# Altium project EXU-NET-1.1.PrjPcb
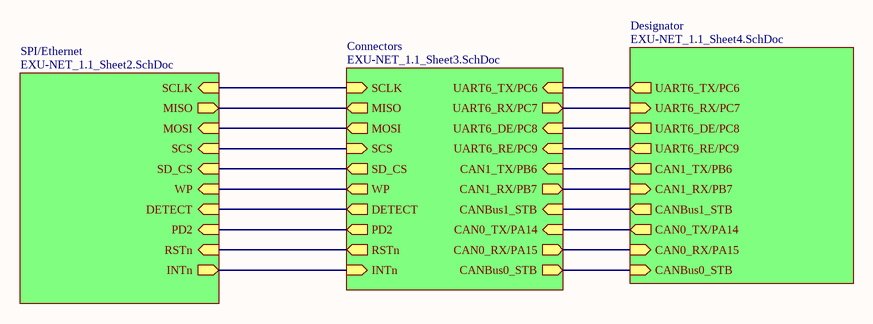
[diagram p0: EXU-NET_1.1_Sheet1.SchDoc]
5 sheets, 112 parts. Net scope: hierarchical (ports join the sheet entries above them; power ports are global).
Board file: EXU-NET_1.1.PcbDoc
Sheets:
  EXU-NET_1.1_Sheet1.SchDoc
    SPI/Ethernet = EXU-NET_1.1_Sheet2.SchDoc
    Connectors = EXU-NET_1.1_Sheet3.SchDoc
    Designator = EXU-NET_1.1_Sheet4.SchDoc
  EXU-NET_1.1_Sheet5.SchDoc

## Sheet EXU-NET_1.1_Sheet1.SchDoc
size A3; SheetNumber: 1; SheetTotal: 5; prj: EXU-NET; Ver: 1.1; Ti: MAIN LIST

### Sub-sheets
Connectors = EXU-NET_1.1_Sheet3.SchDoc: MOSI (out), MISO (out), SCLK (in), SCS (in), SD_CS (out), WP (out), DETECT (out), PD2 (out), CAN1_RX/PB7 (out), CAN1_TX/PB6 (in), UART6_RE/PC9 (in), UART6_DE/PC8 (in), UART6_RX/PC7 (out), UART6_TX/PC6 (in), CANBus1_STB (in), CANBus0_STB (out), CAN0_RX/PA15 (out), CAN0_TX/PA14 (in), RSTn (out), INTn (in)
Designator = EXU-NET_1.1_Sheet4.SchDoc: UART6_TX/PC6 (out), UART6_RX/PC7 (in), UART6_DE/PC8 (out), UART6_RE/PC9 (out), CAN1_TX/PB6 (out), CAN1_RX/PB7 (in), CANBus1_STB (out), CAN0_TX/PA14 (out), CAN0_RX/PA15 (in), CANBus0_STB (in)
SPI/Ethernet = EXU-NET_1.1_Sheet2.SchDoc: MOSI (in), SCS (in), SCLK (in), MISO (out), PD2 (in), DETECT (in), WP (in), SD_CS (in), RSTn (in), INTn (out)

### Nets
CAN0_RX/PA15: sheet Connectors/CAN0_RX/PA15, sheet Designator/CAN0_RX/PA15
CAN0_TX/PA14: sheet Connectors/CAN0_TX/PA14, sheet Designator/CAN0_TX/PA14
CAN1_RX/PB7: sheet Connectors/CAN1_RX/PB7, sheet Designator/CAN1_RX/PB7
CAN1_TX/PB6: sheet Connectors/CAN1_TX/PB6, sheet Designator/CAN1_TX/PB6
CANBus0_STB: sheet Connectors/CANBus0_STB, sheet Designator/CANBus0_STB
CANBus1_STB: sheet Connectors/CANBus1_STB, sheet Designator/CANBus1_STB
MISO: sheet SPI/Ethernet/MISO, sheet Connectors/MISO
MOSI: sheet SPI/Ethernet/MOSI, sheet Connectors/MOSI
RSTn: sheet SPI/Ethernet/RSTn, sheet Connectors/RSTn
SCLK: sheet SPI/Ethernet/SCLK, sheet Connectors/SCLK
SCS: sheet SPI/Ethernet/SCS, sheet Connectors/SCS
UART6_DE/PC8: sheet Connectors/UART6_DE/PC8, sheet Designator/UART6_DE/PC8
UART6_RE/PC9: sheet Connectors/UART6_RE/PC9, sheet Designator/UART6_RE/PC9
UART6_RX/PC7: sheet Connectors/UART6_RX/PC7, sheet Designator/UART6_RX/PC7
UART6_TX/PC6: sheet Connectors/UART6_TX/PC6, sheet Designator/UART6_TX/PC6
NetR53_2: sheet SPI/Ethernet/INTn, sheet Connectors/INTn
(unnamed): sheet SPI/Ethernet/PD2, sheet Connectors/PD2
(unnamed): sheet SPI/Ethernet/DETECT, sheet Connectors/DETECT  [a separate net that carries the same name]
(unnamed): sheet SPI/Ethernet/WP, sheet Connectors/WP  [a separate net that carries the same name]
(unnamed): sheet SPI/Ethernet/SD_CS, sheet Connectors/SD_CS  [a separate net that carries the same name]

## Sheet EXU-NET_1.1_Sheet2.SchDoc
size A3; SheetNumber: 2; SheetTotal: 5; TI: SPI/Ethernet; Prj: EXU-ETH; VER: 1.1
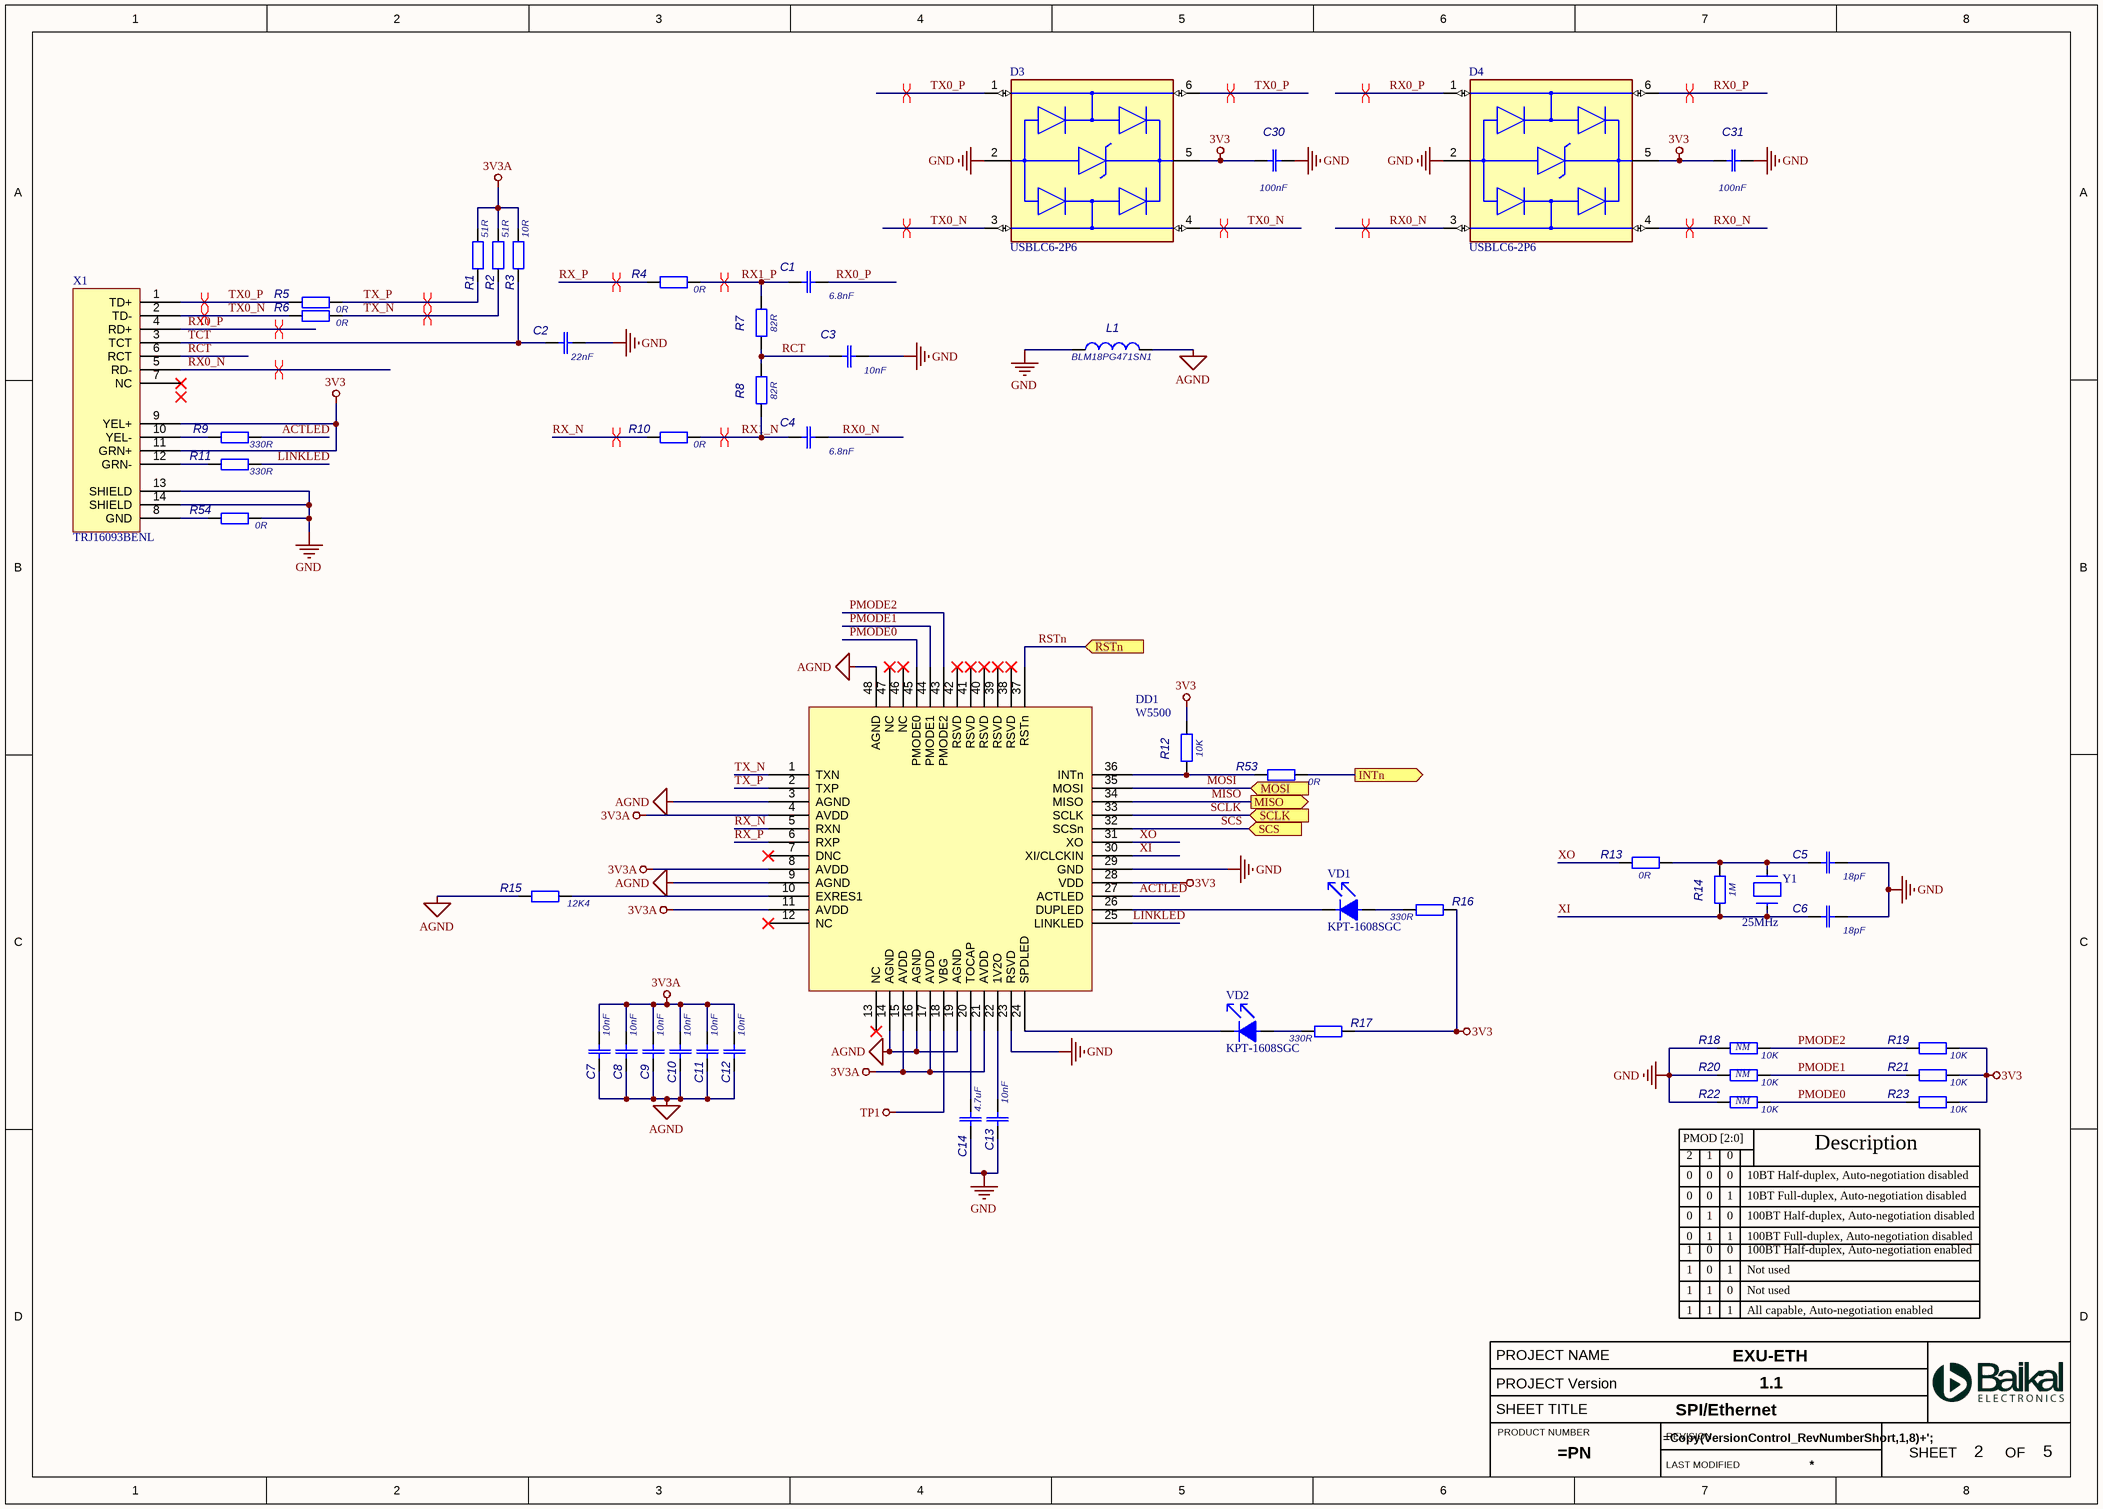
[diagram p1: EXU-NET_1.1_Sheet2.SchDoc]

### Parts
C1  6.8nF  [C0603_CAPC1608X09N]
C2  22nF  [C0603_CAPC1608X09N]
C3  10nF  [C0603_CAPC1608X09N]
C4  6.8nF  [C0603_CAPC1608X09N]
C5  18pF  [C0603_CAPC1608X09N]
C6  18pF  [C0603_CAPC1608X09N]
C7  10nF  [C0603_CAPC1608X09N]
C8  10nF  [C0603_CAPC1608X09N]
C9  10nF  [C0603_CAPC1608X09N]
C10  10nF  [C0603_CAPC1608X09N]
C11  10nF  [C0603_CAPC1608X09N]
C12  10nF  [C0603_CAPC1608X09N]
C13  10nF  [C0603_CAPC1608X09N]
C14  4.7uF  [C0603_CAPC1608X09N]
C30  100nF  [C0603_CAPC1608X09N]
C31  100nF  [C0603_CAPC1608X09N]
D3  USBLC6-2P6  [FP-SOT-666-MFG]
D4  USBLC6-2P6  [FP-SOT-666-MFG]
DD1  W5500  [W5500]
L1  BLM18PG471SN1  [I0603_INDC1608X10N]
R1  51R  [R0603_RESC1608X06N]
R2  51R  [R0603_RESC1608X06N]
R3  10R  [R0603_RESC1608X06N]
R4  0R  [R0603_RESC1608X06N]
R5  0R  [R0603_RESC1608X06N]
R6  0R  [R0603_RESC1608X06N]
R7  82R  [R0603_RESC1608X06N]
R8  82R  [R0603_RESC1608X06N]
R9  330R  [R0603_RESC1608X06N]
R10  0R  [R0603_RESC1608X06N]
R11  330R  [R0603_RESC1608X06N]
R12  10K  [R0603_RESC1608X06N]
R13  0R  [R0603_RESC1608X06N]
R14  1M  [R0603_RESC1608X06N]
R15  12K4  [R0603_RESC1608X06N]
R16  330R  [R0603_RESC1608X06N]
R17  330R  [R0603_RESC1608X06N]
R18  10K  DNP: NM  [R0603_RESC1608X06N]
R19  10K  [R0603_RESC1608X06N]
R20  10K  DNP: NM  [R0603_RESC1608X06N]
R21  10K  [R0603_RESC1608X06N]
R22  10K  DNP: NM  [R0603_RESC1608X06N]
R23  10K  [R0603_RESC1608X06N]
R53  0R  [R0603_RESC1608X06N]
R54  0R  [R0603_RESC1608X06N]
VD1  KPT-1608SGC  [light diode 0603]
VD2  KPT-1608SGC  [light diode 0603]
X1  TRJ16093BENL  [TRJ16093BENL]
Y1  25MHz  [SJK-6C-25.000-16-30-30-C-50-H]

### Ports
INTn (out, see EXU-NET_1.1_Sheet1[5B], EXU-NET_1.1_Sheet3[7D]), MISO (out, see EXU-NET_1.1_Sheet1[5C], EXU-NET_1.1_Sheet3[3C]), MOSI (in, see EXU-NET_1.1_Sheet1[5C], EXU-NET_1.1_Sheet3[3C]), RSTn (in, see EXU-NET_1.1_Sheet1[5B], EXU-NET_1.1_Sheet3[7D]), SCLK (in, see EXU-NET_1.1_Sheet1[5C], EXU-NET_1.1_Sheet3[3C]), SCS (in, see EXU-NET_1.1_Sheet1[5C], EXU-NET_1.1_Sheet3[3C])

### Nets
3V3: C30.1 C31.1 D3.5(VBUS) D4.5(VBUS) DD1.28(VDD) R12.2 R16.1 R17.1 R19.2 R21.2 R23.2 X1.9(YEL+) X1.11(GRN+)
3V3A: C7.2 C8.2 C9.2 C10.2 C11.2 C12.2 DD1.4(AVDD) DD1.8(AVDD) DD1.11(AVDD) DD1.15(AVDD) DD1.17(AVDD) DD1.21(AVDD) R1.2 R2.2 R3.2
AGND: C7.1 C8.1 C9.1 C10.1 C11.1 C12.1 DD1.3(AGND) DD1.9(AGND) DD1.14(AGND) DD1.16(AGND) DD1.19(AGND) DD1.48(AGND) L1.1 R15.1
GND: C2.2 C3.2 C5.2 C6.2 C13.1 C14.1 C30.2 C31.2 D3.2(GND) D4.2(GND) DD1.23(RSVD) DD1.29(GND) L1.2 R18.1 R20.1 R22.1 R54.2 X1.13(SHIELD) X1.14(SHIELD)
TP1: DD1.18(VBG)
ACTLED: DD1.27(ACTLED) R9.2
LINKLED: DD1.25(LINKLED) R11.2
MISO: DD1.34(MISO) ; port MISO
MOSI: DD1.35(MOSI) ; port MOSI
PMODE0: DD1.45(PMODE0) R22.2 R23.1
PMODE1: DD1.44(PMODE1) R20.2 R21.1
PMODE2: DD1.43(PMODE2) R18.2 R19.1
RCT: C3.1 R7.1 R8.2 X1.6(RCT)
RSTn: DD1.37(RSTn) ; port RSTn
RX0_N: C4.2 D4.3(I/O2) D4.4(I/O2) X1.5(RD-)
RX0_P: C1.2 D4.1(I/O1) D4.6(I/O1) X1.4(RD+)
RX1_N: C4.1 R8.1 R10.2
RX1_P: C1.1 R4.2 R7.2
RX_N: DD1.5(RXN) R10.1
RX_P: DD1.6(RXP) R4.1
SCLK: DD1.33(SCLK) ; port SCLK
SCS: DD1.32(SCSn) ; port SCS
TCT: C2.1 R3.1 X1.3(TCT)
TX0_N: D3.3(I/O2) D3.4(I/O2) R6.1 X1.2(TD-)
TX0_P: D3.1(I/O1) D3.6(I/O1) R5.1 X1.1(TD+)
TX_N: DD1.1(TXN) R2.1 R6.2
TX_P: DD1.2(TXP) R1.1 R5.2
XI: C6.1 DD1.30(XI/CLCKIN) R14.1 Y1.1
XO: DD1.31(XO) R13.1
NetC5_1: C5.1 R13.2 R14.2 Y1.2
NetC13_2: C13.2 DD1.22(1V2O)
NetC14_2: C14.2 DD1.20(TOCAP)
NetDD1_10: DD1.10(EXRES1) R15.2
NetDD1_24: DD1.24(SPDLED) VD2.2
NetDD1_26: DD1.26(DUPLED) VD1.2
NetDD1_36: DD1.36(INTn) R12.1 R53.1
NetR9_1: R9.1 X1.10(YEL-)
NetR11_1: R11.1 X1.12(GRN-)
NetR16_2: R16.2 VD1.1
NetR17_2: R17.2 VD2.1
NetR53_2: R53.2 ; port INTn
NetR54_1: R54.1 X1.8(GND)

Not connected (* = marked no-connect by the designer): DD1 7(DNC)* 12(NC)* 13(NC)* 38(RSVD)* 39(RSVD)* 40(RSVD)* 41(RSVD)* 42(RSVD)* 46(NC)* 47(NC)*; X1 7(NC)*

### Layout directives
differential pair: RX0_N, RX0_P, RX1_N, RX1_P, RX_N, RX_P, TX0_N, TX0_P, TX_N, TX_P

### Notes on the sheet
- (near R22) PMOD [2:0]
- 2
- 0
- 1
- 10BT Half-duplex, Auto-negotiation disabled
- (near R23) Description
- 10BT Full-duplex, Auto-negotiation disabled
- 100BT Half-duplex, Auto-negotiation disabled
- 100BT Full-duplex, Auto-negotiation disabled
- 100BT Half-duplex, Auto-negotiation enabled
- Not used
- All capable, Auto-negotiation enabled

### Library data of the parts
C1 C4 = CC0603KRX7R9BB682: 0603 6,8nF ±10% 50V; Manufacturer: YAGEO; ValueBOM: 6800пФ ±10% 50В X7R 0603; ValueSCH: 6800 50V; ModelSTEP: C:\AltiumLib\ALTIUM\MODEL\STEP\Capacitor\C0603_CAPC1608X09.Step; Designer: Dudarev; EOL: NO
C2 = CC0603KRX7R9BB223: 0603 22nF ±10% 50V; Manufacturer: YAGEO; ValueBOM: 0,022мкФ ±10% 50В X7R 0603; ValueSCH: 0,022u 50V; ModelSTEP: C:\AltiumLib\ALTIUM\MODEL\STEP\Capacitor\C0603_CAPC1608X09.Step; Designer: Dudarev; EOL: NO
C3 C7-C13 = CC0603KRX7R9BB103: 0603 10nF ±10% 50V; Manufacturer: YAGEO; ValueBOM: 0,01мкФ ±10% 50В X7R 0603; ModelSTEP: C:\AltiumLib\ALTIUM\MODEL\STEP\Capacitor\C0603_CAPC1608X09.Step; Designer: Dudarev; EOL: NO
C5 C6 = CC0603JRNPO9BN180: 0603 18pF ±10% 50V; Manufacturer: YAGEO; ValueBOM: 18пФ ±5% 50В NP0 0603; ValueSCH: 18 50V; ModelSTEP: C:\AltiumLib\ALTIUM\MODEL\STEP\Capacitor\C0603_CAPC1608X09.Step; Designer: Pashinskiy; EOL: NO
C14 = CC0603KRX7R5BB475: 0603 4,7uF ±10% 6,3V; Manufacturer: YAGEO; ValueBOM: 4,7мкФ ±10% 6,3В X7R 0603; ValueSCH: 4,7u 6,3V; ModelSTEP: C:\AltiumLib\ALTIUM\MODEL\STEP\Capacitor\C0603_CAPC1608X09.Step; Designer: Dudarev; EOL: NO
C30 C31 = CC0603KRX7R9BB104: 0603 100nF ±10% 50V; Manufacturer: YAGEO; ValueBOM: 0,1мкФ ±10% 50В X7R 0603; ModelSTEP: C:\AltiumLib\ALTIUM\MODEL\STEP\Capacitor\C0603_CAPC1608X09.Step; Designer: Dudarev; EOL: NO
D3 D4 = CMP-12225-000058-1: TVS DIODE 5.25V 17V SOT666; Min Breakdown Voltage: 6V; Power Line Protection: Yes; Element Configuration: Dual; Test Current: 1mA; Working Voltage: 5V; Number of Channels: 2; Max Reverse Leakage Current: 150nA; Direction: Unidirectional; Peak Pulse Current: 5A; Number of Elements: 1; Capacitance: 3.5pF
DD1 = W5500: W5500, TCP/IP Ethernet Controller IC, [LQFP-48]
L1 = BLM18PG471SN1: EMI Inductive Filter for Power lines 470Ohm 25% 100MHz 1A 200mOhm DCR 0603 T/R; Manufacturer: Murata
R1 R2 = RC0603JR-0751RL: 0603 51 Ohm±5% 0,1W; Manufacturer: YAGEO; ValueBOM: 51Ом   75В 200ppm 0603; ModelSTEP: C:\AltiumLib\ALTIUM\MODEL\STEP\Resistor\R0603_RESC1005X04.step; Designer: Dudarev; EOL: NO
R3 = RC0603JR-0710RL: 0603 10 Ohm±5% 0,1W; Manufacturer: YAGEO; ValueBOM: 10Ом   75В 300ppm 0603; ModelSTEP: C:\AltiumLib\ALTIUM\MODEL\STEP\Resistor\R0603_RESC1005X04.step; Designer: Dudarev; EOL: NO
R4-R6 R10 R13 R53 R54 = RC0603JR-070RL: 0603 0 Ohm 0,1W; Manufacturer: YAGEO; ValueBOM: 0Ом   75В 300ppm 0603; ModelSTEP: C:\AltiumLib\ALTIUM\MODEL\STEP\Resistor\R0603_RESC1005X04.step; Designer: Dudarev; EOL: NO
R7 R8 = RC0603JR-0782RL: 0603 82 Ohm±5% 0,1W; Manufacturer: YAGEO; ValueBOM: 82Ом   75В 200ppm 0603; ModelSTEP: C:\AltiumLib\ALTIUM\MODEL\STEP\Resistor\R0603_RESC1005X04.step; Designer: Dudarev; EOL: NO
R9 R11 R16 R17 = RC0603JR-07330RL: 0603 330 Ohm±5% 0,1W; Manufacturer: YAGEO; ValueBOM: 330Ом   75В 150ppm 0603; ModelSTEP: C:\AltiumLib\ALTIUM\MODEL\STEP\Resistor\R0603_RESC1005X04.step; Designer: Dudarev; EOL: NO
R12 R18-R23 = RC0603JR-0710KL: 0603 10 kOhm±5% 0,1W; Manufacturer: YAGEO; ValueBOM: 10кОм   75В 150ppm 0603; ModelSTEP: C:\AltiumLib\ALTIUM\MODEL\STEP\Resistor\R0603_RESC1005X04.step; Designer: Dudarev; EOL: NO
R14 = RC0603JR-071ML: 0603 1 MOhm±5% 0,1W; Manufacturer: YAGEO; ValueBOM: 1МОм   75В 150ppm 0603; ModelSTEP: C:\AltiumLib\ALTIUM\MODEL\STEP\Resistor\R0603_RESC1005X04.step; Designer: Dudarev; EOL: NO
R15 = RC0603FR-0712K4L: 0603 12,4 kOhm±1% 0,1W; Manufacturer: YAGEO; ValueBOM: 12,4кОм   75В 150ppm 0603; ValueSCH: 12,4K; ModelSTEP: C:\AltiumLib\ALTIUM\MODEL\STEP\Resistor\R0603_RESC1005X04.step; Designer: Dudarev; EOL: NO
VD1 VD2 = KPT-1608SGC: Green LED SMD 0603
X1 = TRJ16093BENL: Connector ecr. "socket" RJ-45 C matching. 10/100Base-TX filter (1:1), 2 tops. the LED. (left green/right yellow), without petals, -40 to + 85 °C, etc. angle per board, Lc = 21.5 mm
Y1 = SJK-6C-25.000-16-30-30-C-50-H: 25.000Мгц, HC-49SM

## Sheet EXU-NET_1.1_Sheet3.SchDoc
size A3; SheetNumber: 3; SheetTotal: 5; ti: Connectors; prj: EXU-ETH; ver: 1.1
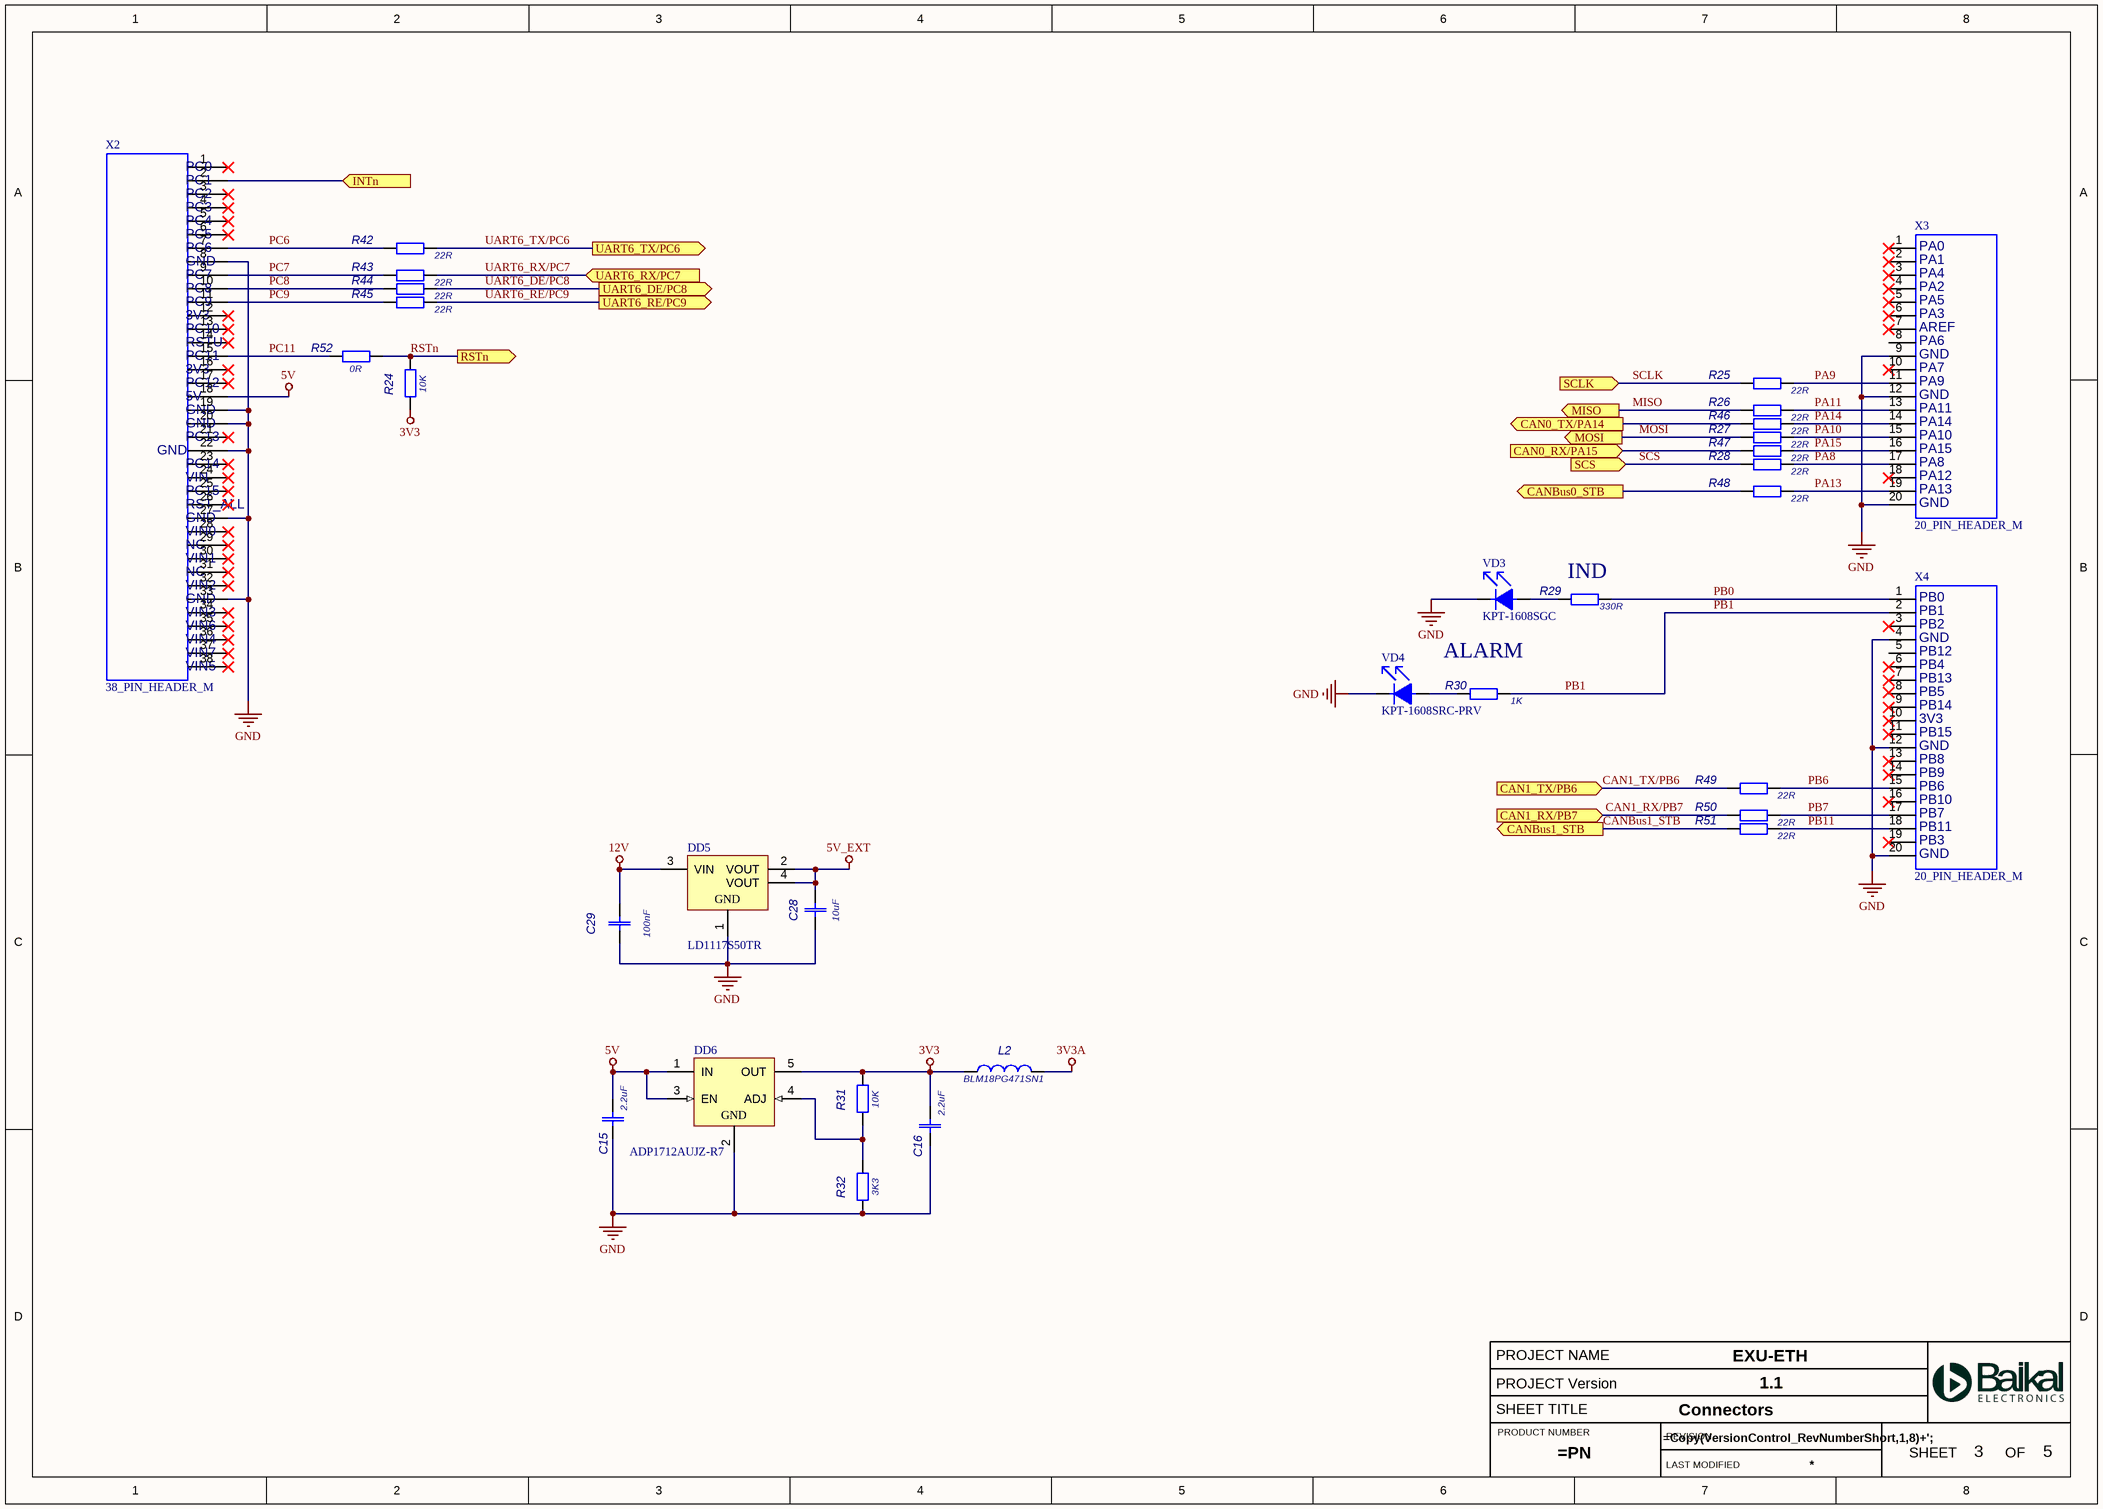
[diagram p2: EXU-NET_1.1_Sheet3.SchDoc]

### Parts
C15  2.2uF  [C0603_CAPC1608X09N]
C16  2.2uF  [C0603_CAPC1608X09N]
C28  10uF  [C0805_CAPC2012X13N]
C29  100nF  [C0603_CAPC1608X09N]
DD5  LD1117S50TR  [SOT-223_L]
DD6  ADP1712AUJZ-R7  [ADI-UJ-5_M]
L2  BLM18PG471SN1  [I0603_INDC1608X10N]
R24  10K  [R0603_RESC1608X06N]
R25  22R  [R0603_RESC1608X06N]
R26  22R  [R0603_RESC1608X06N]
R27  22R  [R0603_RESC1608X06N]
R28  22R  [R0603_RESC1608X06N]
R29  330R  [R0603_RESC1608X06N]
R30  1K  [R0603_RESC1608X06N]
R31  10K  [R0603_RESC1608X06N]
R32  3K3  [R0603_RESC1608X06N]
R42  22R  [R0603_RESC1608X06N]
R43  22R  [R0603_RESC1608X06N]
R44  22R  [R0603_RESC1608X06N]
R45  22R  [R0603_RESC1608X06N]
R46  22R  [R0603_RESC1608X06N]
R47  22R  [R0603_RESC1608X06N]
R48  22R  [R0603_RESC1608X06N]
R49  22R  [R0603_RESC1608X06N]
R50  22R  [R0603_RESC1608X06N]
R51  22R  [R0603_RESC1608X06N]
R52  0R  [R0603_RESC1608X06N]
VD3  KPT-1608SGC  [light diode 0603]
VD4  KPT-1608SRC-PRV  [light diode 0603]
X2  38_PIN_HEADER_M  [38_PIN_HEADER_M]
X3  20_PIN_HEADER_M  [20_PIN_HEADER_M]
X4  20_PIN_HEADER_M  [20_PIN_HEADER_M]

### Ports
CAN0_RX/PA15 (in, see EXU-NET_1.1_Sheet1[3B], EXU-NET_1.1_Sheet4[6B]), CAN0_TX/PA14 (out, see EXU-NET_1.1_Sheet1[3B], EXU-NET_1.1_Sheet4[6B]), CAN1_RX/PB7 (in, see EXU-NET_1.1_Sheet1[3B], EXU-NET_1.1_Sheet4[6C]), CAN1_TX/PB6 (in, see EXU-NET_1.1_Sheet1[3C], EXU-NET_1.1_Sheet4[6C]), CANBus0_STB (out, see EXU-NET_1.1_Sheet1[3B], EXU-NET_1.1_Sheet4[6B]), CANBus1_STB (out, see EXU-NET_1.1_Sheet1[3B], EXU-NET_1.1_Sheet4[6C]), INTn (in, see EXU-NET_1.1_Sheet1[4B], EXU-NET_1.1_Sheet2[3B]), MISO (out, see EXU-NET_1.1_Sheet1[4C], EXU-NET_1.1_Sheet2[4B]), MOSI (out, see EXU-NET_1.1_Sheet1[4C], EXU-NET_1.1_Sheet2[4B]), RSTn (out, see EXU-NET_1.1_Sheet1[4B], EXU-NET_1.1_Sheet2[4C]), SCLK (in, see EXU-NET_1.1_Sheet1[4C], EXU-NET_1.1_Sheet2[4B]), SCS (in, see EXU-NET_1.1_Sheet1[4C], EXU-NET_1.1_Sheet2[4B]), UART6_DE/PC8 (out, see EXU-NET_1.1_Sheet1[3C], EXU-NET_1.1_Sheet4[6D]), UART6_RE/PC9 (out, see EXU-NET_1.1_Sheet1[3C], EXU-NET_1.1_Sheet4[6D]), UART6_RX/PC7 (in, see EXU-NET_1.1_Sheet1[3C], EXU-NET_1.1_Sheet4[7D]), UART6_TX/PC6 (out, see EXU-NET_1.1_Sheet1[3C], EXU-NET_1.1_Sheet4[6D])

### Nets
3V3: C16.2 DD6.5(OUT) L2.2 R24.1 R31.2
3V3A: L2.1
5V: C15.2 DD6.1(IN) DD6.3(EN) X2.18
5V_EXT: C28.2 DD5.2(VOUT) DD5.4(VOUT)
12V: C29.2 DD5.3(VIN)
GND: C15.1 C16.1 C28.1 C29.1 DD5.1(GND) DD6.2(GND) R32.1 VD3.2 VD4.2 X2.8 X2.19 X2.20 X2.22 X2.27 X2.33 X3.9 X3.12 X3.20 X4.4 X4.12 X4.20
CAN0_RX/PA15: R47.1 ; port CAN0_RX/PA15
CAN0_TX/PA14: R46.1 ; port CAN0_TX/PA14
CAN1_RX/PB7: R50.1 ; port CAN1_RX/PB7
CAN1_TX/PB6: R49.1 ; port CAN1_TX/PB6
CANBus0_STB: R48.1 ; port CANBus0_STB
CANBus1_STB: R51.1 ; port CANBus1_STB
MISO: R26.1 ; port MISO
MOSI: R27.1 ; port MOSI
PA8: R28.2 X3.17
PA9: R25.2 X3.11
PA10: R27.2 X3.15
PA11: R26.2 X3.13
PA13: R48.2 X3.19
PA14: R46.2 X3.14
PA15: R47.2 X3.16
PB0: R29.2 X4.1
PB1: R30.2 X4.2
PB6: R49.2 X4.15
PB7: R50.2 X4.17
PB11: R51.2 X4.18
PC6: R42.1 X2.7
PC7: R43.1 X2.9
PC8: R44.1 X2.10
PC9: R45.1 X2.11
PC11: R52.1 X2.15
RSTn: R24.2 R52.2 ; port RSTn
SCLK: R25.1 ; port SCLK
SCS: R28.1 ; port SCS
UART6_DE/PC8: R44.2 ; port UART6_DE/PC8
UART6_RE/PC9: R45.2 ; port UART6_RE/PC9
UART6_RX/PC7: R43.2 ; port UART6_RX/PC7
UART6_TX/PC6: R42.2 ; port UART6_TX/PC6
NetDD6_4: DD6.4(ADJ) R31.1 R32.2
NetR29_1: R29.1 VD3.1
NetR30_1: R30.1 VD4.1
NetR53_2: X2.2 ; port INTn

Not connected (* = marked no-connect by the designer): X2 1* 3* 4* 5* 6* 12* 13* 14* 16* 17* 21* 23* 24* 25* 26* 28* 29* 30* 31* 32* 34* 35* 36* 37* 38*; X3 1* 2* 3* 4* 5* 6* 7* 8 10* 18*; X4 3* 5 6* 7* 8 9* 10* 11* 13* 14* 16* 19*

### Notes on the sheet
- (near X2) PC0
- (near X2) PC1
- (near X2) PC2
- (near X2) PC3
- (near X2) PC4
- (near X2) PC5
- (near X2) GND
- (near X2) PC6
- (near X2) PC7
- (near X2) PC8
- (near X2) PC9
- (near X3) PA0
- (near X3) PA1
- (near X3) PA2
- (near X3) PA3
- (near X3) PA4
- (near X3) PA5
- (near X2) 3V3
- (near X2) PC10
- (near X2) RSTU
- (near X2) PC11
- (near X3) PA6
- (near X3) AREF
- (near X3) GND
- (near X3) PA7
- (near X2) PC12
- (near X2) 5V
- (near X2) PC13
- (near X3) PA9
- (near X3) PA11
- (near X3) PA14
- (near X3) PA10
- (near X3) PA15
- (near X2) PC14
- (near X2) VIN
- (near X2) PC15
- (near X2) RST_ALL
- (near X3) PA8
- (near X3) PA12
- (near X3) PA13
- (near X2) VIN0
- (near X2) VIN1
- (near X2) NC
- (near R29) IND
- (near X2) VIN2
- (near X2) VIN3
- (near X2) VIN4
- (near X2) VIN6
- (near X4) PB0
- (near X4) PB1
- (near X4) PB2
- (near X4) GND
- (near X2) VIN5
- (near X2) VIN7
- ALARM
- (near X4) PB12
- (near X4) PB4
- (near X4) PB13
- (near X4) PB5
- (near X4) PB14
- (near X4) 3V3
- (near X4) PB15
- (near X4) PB8
- (near X4) PB9
- (near X4) PB6
- (near X4) PB10
- (near X4) PB7
- (near X4) PB11
- (near X4) PB3

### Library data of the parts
C15 C16 = CC0603KRX7R7BB225: 0603 2,2uF ±10% 16V; Manufacturer: YAGEO; ValueBOM: 2,2мкФ ±10%; ValueSCH: 2,2u 16V; ModelSTEP: C:\AltiumLib\ALTIUM\MODEL\STEP\Capacitor\C0603_CAPC1608X09.Step; Designer: Dudarev; EOL: NO
C28 = CC0805KRX7R7BB106: Конденсатор керамический (MLCC) общего назначения 0805; Manufacturer: YAGEO; ValueBOM: 10мкФ ±10% 16В X7R 0805; ValueSCH: 10u 16V; ModelSTEP: C:\AltiumLib\ALTIUM\MODEL\STEP\Capacitor\C0805_CAPC2012X13.Step; Designer: Dudarev; EOL: NO
C29 = CC0603KRX7R9BB104: as C30 on sheet EXU-NET_1.1_Sheet2
DD5 = CMP-0244-00312-1: Fixed Low Drop Positive Voltage Regulator, 5V, 4-Pin SOT-223, Tape and Reel
DD6 = CMP-0786-00408-1: 300 mA, Low Dropout CMOS Linear Regulator, 2.5 to 5.5 V Vin, 0.8 to 5 V Vout, Industrial, 5-pin SOT23 (UJ-5), Reel; Manufacturer: Analog Devices; Vin (min) (V): 2.5; Supply Current IGND @ Small Load: 60uA; Vin (max) (V): 5.5; Iout max: 300mA; Vout Adjustable Range: 0.8V to 5V
L2 = BLM18PG471SN1: as L1 on sheet EXU-NET_1.1_Sheet2
R24 R31 = RC0603JR-0710KL: as R12 on sheet EXU-NET_1.1_Sheet2
R25-R28 R42-R51 = RC0603JR-0722RL: 0603 22 Ohm±5% 0,1W; Manufacturer: YAGEO; ValueBOM: 22Ом   75В 200ppm 0603; ModelSTEP: C:\AltiumLib\ALTIUM\MODEL\STEP\Resistor\R0603_RESC1005X04.step; Designer: Dudarev; EOL: NO
R29 = RC0603JR-07330RL: as R9 on sheet EXU-NET_1.1_Sheet2
R30 = RC0603JR-071KL: 0603 1 kOhm±5% 0,1W; Manufacturer: YAGEO; ValueBOM: 1кОм   75В 150ppm 0603; ModelSTEP: C:\AltiumLib\ALTIUM\MODEL\STEP\Resistor\R0603_RESC1005X04.step; Designer: Dudarev; EOL: NO
R32 = RC0603JR-073K3L: 0603 3,3 kOhm±5% 0,1W; Manufacturer: YAGEO; ValueBOM: 3,3кОм   75В 150ppm 0603; ValueSCH: 3,3K; ModelSTEP: C:\AltiumLib\ALTIUM\MODEL\STEP\Resistor\R0603_RESC1005X04.step; Designer: Dudarev; EOL: NO
R52 = RC0603JR-070RL: as R4 on sheet EXU-NET_1.1_Sheet2
VD3 = KPT-1608SGC: Green LED SMD 0603
VD4 = KPT-1608SRC-PRV: Red LED SMD 0603

## Sheet EXU-NET_1.1_Sheet4.SchDoc
size A3; SheetNumber: 4; SheetTotal: 5; Prj: EXU-ETH; Ver: 1.1; Ti: CAN & RS485
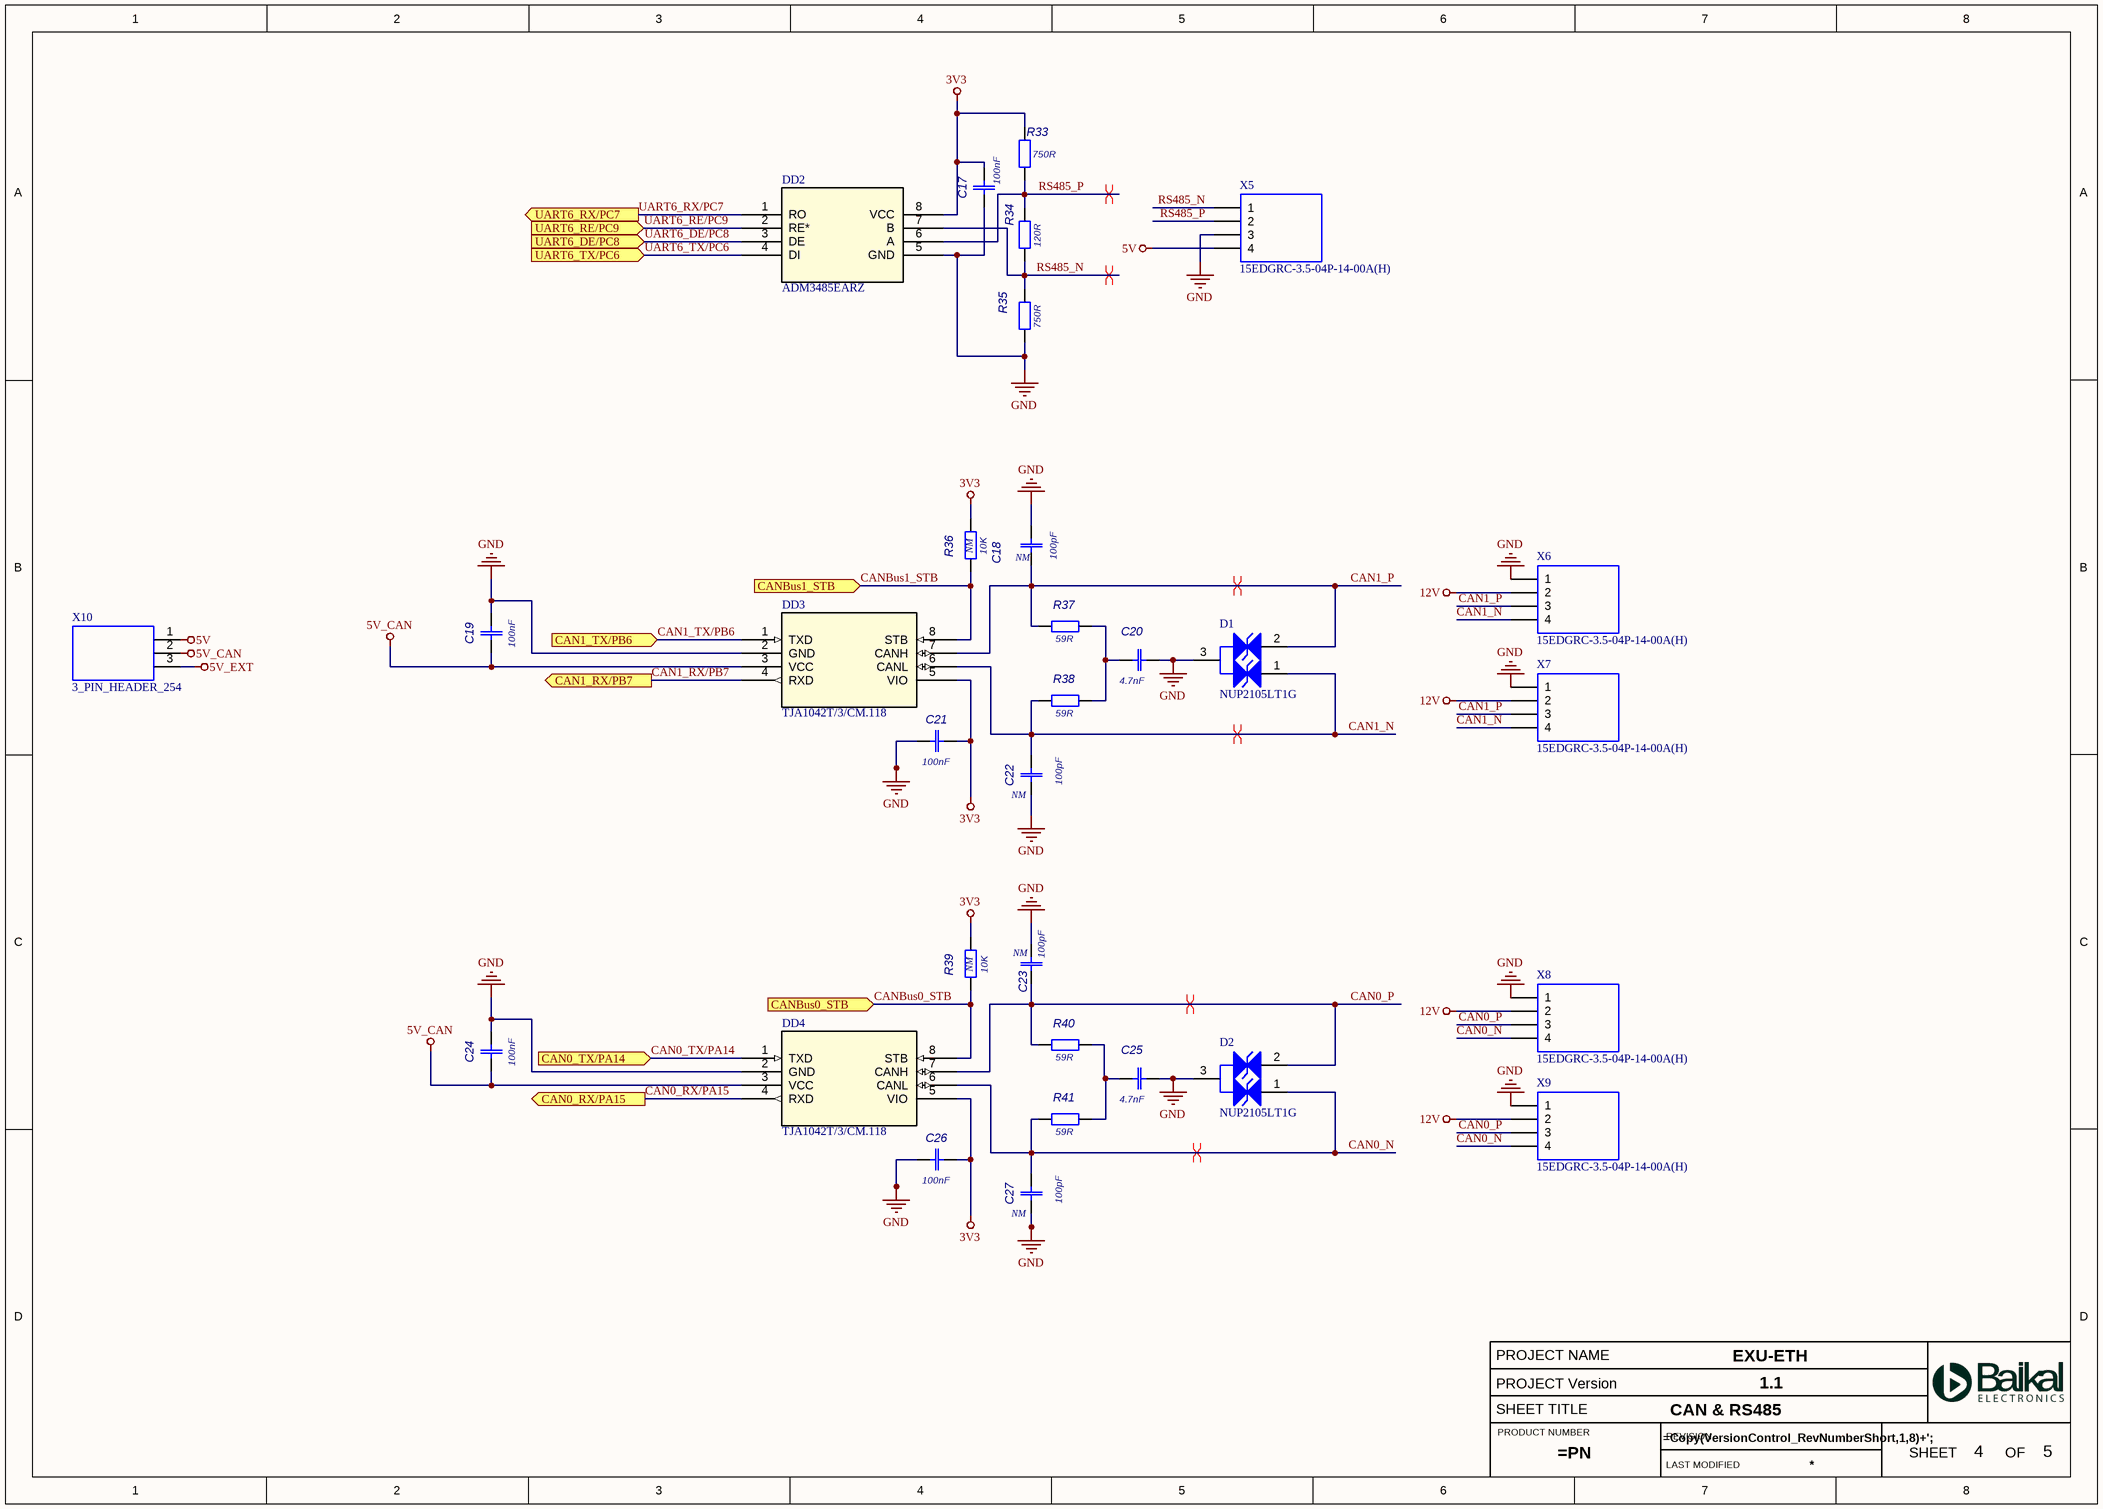
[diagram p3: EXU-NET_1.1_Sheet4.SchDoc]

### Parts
C17  100nF  [C0603_CAPC1608X09N]
C18  100pF  DNP: NM  [C0603_CAPC1608X09N]
C19  100nF  [C0603_CAPC1608X09N]
C20  4.7nF  [C0603_CAPC1608X09N]
C21  100nF  [C0603_CAPC1608X09N]
C22  100pF  DNP: NM  [C0603_CAPC1608X09N]
C23  100pF  DNP: NM  [C0603_CAPC1608X09N]
C24  100nF  [C0603_CAPC1608X09N]
C25  4.7nF  [C0603_CAPC1608X09N]
C26  100nF  [C0603_CAPC1608X09N]
C27  100pF  DNP: NM  [C0603_CAPC1608X09N]
D1  NUP2105LT1G  [ONSC-SOT-23-3-318-08_V]
D2  NUP2105LT1G  [ONSC-SOT-23-3-318-08_V]
DD2  ADM3485EARZ  [TJA1042T/3/CM.118]
DD3  TJA1042T/3/CM.118  [TJA1042T/3/CM.118]
DD4  TJA1042T/3/CM.118  [TJA1042T/3/CM.118]
R33  750R  [R0603_RESC1608X06N]
R34  120R  [R0603_RESC1608X06N]
R35  750R  [R0603_RESC1608X06N]
R36  10K  DNP: NM  [R0603_RESC1608X06N]
R37  59R  [R1206_RESC3116X07N]
R38  59R  [R1206_RESC3116X07N]
R39  10K  DNP: NM  [R0603_RESC1608X06N]
R40  59R  [R1206_RESC3116X07N]
R41  59R  [R1206_RESC3116X07N]
X5  15EDGRC-3.5-04P-14-00A(H)  [15EDGRC-3.5-04P-14-00A(H)]
X6  15EDGRC-3.5-04P-14-00A(H)  [15EDGRC-3.5-04P-14-00A(H)]
X7  15EDGRC-3.5-04P-14-00A(H)  [15EDGRC-3.5-04P-14-00A(H)]
X8  15EDGRC-3.5-04P-14-00A(H)  [15EDGRC-3.5-04P-14-00A(H)]
X9  15EDGRC-3.5-04P-14-00A(H)  [15EDGRC-3.5-04P-14-00A(H)]
X10  3_PIN_HEADER_254  [3_PIN_HEADER_254]

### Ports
CAN0_RX/PA15 (out, see EXU-NET_1.1_Sheet1[3B], EXU-NET_1.1_Sheet3[3C]), CAN0_TX/PA14 (in, see EXU-NET_1.1_Sheet1[3B], EXU-NET_1.1_Sheet3[3C]), CAN1_RX/PB7 (out, see EXU-NET_1.1_Sheet1[3B], EXU-NET_1.1_Sheet3[3B]), CAN1_TX/PB6 (in, see EXU-NET_1.1_Sheet1[3C], EXU-NET_1.1_Sheet3[3B]), CANBus0_STB (in, see EXU-NET_1.1_Sheet1[3B], EXU-NET_1.1_Sheet3[3C]), CANBus1_STB (in, see EXU-NET_1.1_Sheet1[3B], EXU-NET_1.1_Sheet3[3B]), UART6_DE/PC8 (in, see EXU-NET_1.1_Sheet1[3C], EXU-NET_1.1_Sheet3[6D]), UART6_RE/PC9 (in, see EXU-NET_1.1_Sheet1[3C], EXU-NET_1.1_Sheet3[6D]), UART6_RX/PC7 (out, see EXU-NET_1.1_Sheet1[3C], EXU-NET_1.1_Sheet3[6D]), UART6_TX/PC6 (in, see EXU-NET_1.1_Sheet1[3C], EXU-NET_1.1_Sheet3[6D])

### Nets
3V3: C17.2 C21.2 C26.2 DD2.8(VCC) DD3.5(VIO) DD4.5(VIO) R33.2 R36.2 R39.2
5V: X5.4 X10.1
5V_CAN: C19.1 C24.1 DD3.3(VCC) DD4.3(VCC) X10.2
5V_EXT: X10.3
12V: X6.2 X7.2 X8.2 X9.2
GND: C17.1 C18.2 C19.2 C20.2 C21.1 C22.1 C23.2 C24.2 C25.2 C26.1 C27.1 D1.3(K) D2.3(K) DD2.5(GND) DD3.2(GND) DD4.2(GND) R35.1 X5.3 X6.1 X7.1 X8.1 X9.1
CAN0_N: C27.2 D2.1(K) DD4.6(CANL) R41.1 X8.4 X9.4
CAN0_P: C23.1 D2.2(K) DD4.7(CANH) R40.1 X8.3 X9.3
CAN0_RX/PA15: DD4.4(RXD) ; port CAN0_RX/PA15
CAN0_TX/PA14: DD4.1(TXD) ; port CAN0_TX/PA14
CAN1_N: C22.2 D1.1(K) DD3.6(CANL) R38.1 X6.4 X7.4
CAN1_P: C18.1 D1.2(K) DD3.7(CANH) R37.1 X6.3 X7.3
CAN1_RX/PB7: DD3.4(RXD) ; port CAN1_RX/PB7
CAN1_TX/PB6: DD3.1(TXD) ; port CAN1_TX/PB6
CANBus0_STB: DD4.8(STB) R39.1 ; port CANBus0_STB
CANBus1_STB: DD3.8(STB) R36.1 ; port CANBus1_STB
RS485_N: DD2.7(B) R34.1 R35.2 X5.1
RS485_P: DD2.6(A) R33.1 R34.2 X5.2
UART6_DE/PC8: DD2.3(DE) ; port UART6_DE/PC8
UART6_RE/PC9: DD2.2(RE*) ; port UART6_RE/PC9
UART6_RX/PC7: DD2.1(RO) ; port UART6_RX/PC7
UART6_TX/PC6: DD2.4(DI) ; port UART6_TX/PC6
NetC20_1: C20.1 R37.2 R38.2
NetC25_1: C25.1 R40.2 R41.2

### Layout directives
differential pair: CAN0_N, CAN0_P, CAN1_N, CAN1_P, RS485_N, RS485_P

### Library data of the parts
C17 C19 C21 C24 C26 = CC0603KRX7R9BB104: as C30 on sheet EXU-NET_1.1_Sheet2
C18 C22 C23 C27 = CC0603KRX7R9BB101: 0603 100pF  ±10% 50V; Manufacturer: YAGEO; ValueBOM: 100пФ ±10% 50В X7R 0603; ValueSCH: 100 50V; ModelSTEP: C:\AltiumLib\ALTIUM\MODEL\STEP\Capacitor\C0603_CAPC1608X09.Step; Designer: Dudarev; EOL: NO
C20 C25 = CC0603KRX7R9BB472: 0603 4,7nF ±10% 50V; Manufacturer: YAGEO; ValueBOM: 4700пФ ±10% 50В X7R 0603; ValueSCH: 4700 50V; ModelSTEP: C:\AltiumLib\ALTIUM\MODEL\STEP\Capacitor\C0603_CAPC1608X09.Step; Designer: Dudarev; EOL: NO
D1 D2 = CMP-1063-00164-1: Dual Line CAN Bus Protector, 3-Pin SOT-23, Pb-Free, Tape and Reel; Manufacturer: On Semiconductor; IR Max (uA): 0.1; Number of Lines: 2; Direction: Bidirectional; C Max (pF): 30; PPK Max (W): 350; V(BR) Min (V): 26.2
DD2 = ADM3485EARZ: 3.3 V, Â±15 kV ESD-Protected, RS-485/RS-422 Transceiver (Half Duplex, 12Mbps, DE/RE); Manufacturer: Youtai Semiconductor (UMW)
DD3 DD4 = TJA1042T/3/CM.118: Can interface, SOIC8; Manufacturer: NXP Semiconductor
R33 R35 = RC0603JR-07750RL: 0603 750 Ohm±5% 0,1W; Manufacturer: YAGEO; ValueBOM: 750Ом   75В 150ppm 0603; ModelSTEP: C:\AltiumLib\ALTIUM\MODEL\STEP\Resistor\R0603_RESC1005X04.step; Designer: Dudarev; EOL: NO
R34 = RC0603JR-07120RL: 0603 120 Ohm±5% 0,1W; Manufacturer: YAGEO; ValueBOM: 120Ом   75В 150ppm 0603; ModelSTEP: C:\AltiumLib\ALTIUM\MODEL\STEP\Resistor\R0603_RESC1005X04.step; Designer: Dudarev; EOL: NO
R36 R39 = RC0603JR-0710KL: as R12 on sheet EXU-NET_1.1_Sheet2
R37 R38 R40 R41 = RC1206FR-0759RL: 1206 59 Ohm±1% 0,1W; Manufacturer: YAGEO; ValueBOM: 59Ом 1% 200В 100ppm 1206; ValueSCH: 59 1%; ModelSTEP: C:\AltiumLib\ALTIUM\MODEL\STEP\Resistor\R1206_RESC3116X07.step; Designer: Dudarev; EOL: NO
X5-X9 = 15EDGRC-3.5-04P-14-00A(H): TERM BLOCK HDR 4POS 90DEG 3.5MM; Manufacturer: Degson Electronics
X10 = 3_PIN_HEADER_254: 2,54mm Pitch, 1 Row, 3 Circuits, Vertical, THT

## Sheet EXU-NET_1.1_Sheet5.SchDoc
size A3; SheetNumber: 5; SheetTotal: 5; prj: EXU-NET; ver: 1.1; Ti: Revision History
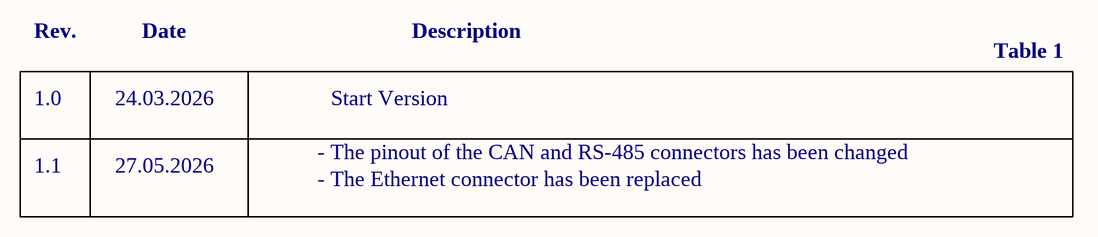
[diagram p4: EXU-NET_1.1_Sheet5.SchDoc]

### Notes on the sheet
- Rev.
- Date
- Description
- Table 1
- 1.0
- 24.03.2026
- - The pinout of the CAN and RS-485 connectors has been changed
- Start Version
- 1.1
- 27.05.2026
- - The Ethernet connector has been replaced

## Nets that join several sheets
3V3: EXU-NET_1.1_Sheet2 (13 pins), EXU-NET_1.1_Sheet3 (5 pins), EXU-NET_1.1_Sheet4 (9 pins)
3V3A: EXU-NET_1.1_Sheet2 (15 pins), EXU-NET_1.1_Sheet3 (L2.1)
5V: EXU-NET_1.1_Sheet3 (C15.2 DD6.1 DD6.3 X2.18), EXU-NET_1.1_Sheet4 (X5.4 X10.1)
5V_EXT: EXU-NET_1.1_Sheet3 (C28.2 DD5.2 DD5.4), EXU-NET_1.1_Sheet4 (X10.3)
12V: EXU-NET_1.1_Sheet3 (C29.2 DD5.3), EXU-NET_1.1_Sheet4 (X6.2 X7.2 X8.2 X9.2)
GND: EXU-NET_1.1_Sheet2 (19 pins), EXU-NET_1.1_Sheet3 (21 pins), EXU-NET_1.1_Sheet4 (22 pins)
CAN0_RX/PA15: EXU-NET_1.1_Sheet3 (R47.1), EXU-NET_1.1_Sheet4 (DD4.4)
CAN0_TX/PA14: EXU-NET_1.1_Sheet3 (R46.1), EXU-NET_1.1_Sheet4 (DD4.1)
CAN1_RX/PB7: EXU-NET_1.1_Sheet3 (R50.1), EXU-NET_1.1_Sheet4 (DD3.4)
CAN1_TX/PB6: EXU-NET_1.1_Sheet3 (R49.1), EXU-NET_1.1_Sheet4 (DD3.1)
CANBus0_STB: EXU-NET_1.1_Sheet3 (R48.1), EXU-NET_1.1_Sheet4 (DD4.8 R39.1)
CANBus1_STB: EXU-NET_1.1_Sheet3 (R51.1), EXU-NET_1.1_Sheet4 (DD3.8 R36.1)
MISO: EXU-NET_1.1_Sheet2 (DD1.34), EXU-NET_1.1_Sheet3 (R26.1)
MOSI: EXU-NET_1.1_Sheet2 (DD1.35), EXU-NET_1.1_Sheet3 (R27.1)
NetR53_2: EXU-NET_1.1_Sheet2 (R53.2), EXU-NET_1.1_Sheet3 (X2.2)
RSTn: EXU-NET_1.1_Sheet2 (DD1.37), EXU-NET_1.1_Sheet3 (R24.2 R52.2)
SCLK: EXU-NET_1.1_Sheet2 (DD1.33), EXU-NET_1.1_Sheet3 (R25.1)
SCS: EXU-NET_1.1_Sheet2 (DD1.32), EXU-NET_1.1_Sheet3 (R28.1)
UART6_DE/PC8: EXU-NET_1.1_Sheet3 (R44.2), EXU-NET_1.1_Sheet4 (DD2.3)
UART6_RE/PC9: EXU-NET_1.1_Sheet3 (R45.2), EXU-NET_1.1_Sheet4 (DD2.2)
UART6_RX/PC7: EXU-NET_1.1_Sheet3 (R43.2), EXU-NET_1.1_Sheet4 (DD2.1)
UART6_TX/PC6: EXU-NET_1.1_Sheet3 (R42.2), EXU-NET_1.1_Sheet4 (DD2.4)

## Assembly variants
Variant of EXU-NET-1.0: not fitted C18 C22 C23 C27 R18 R20 R22 R36 R39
